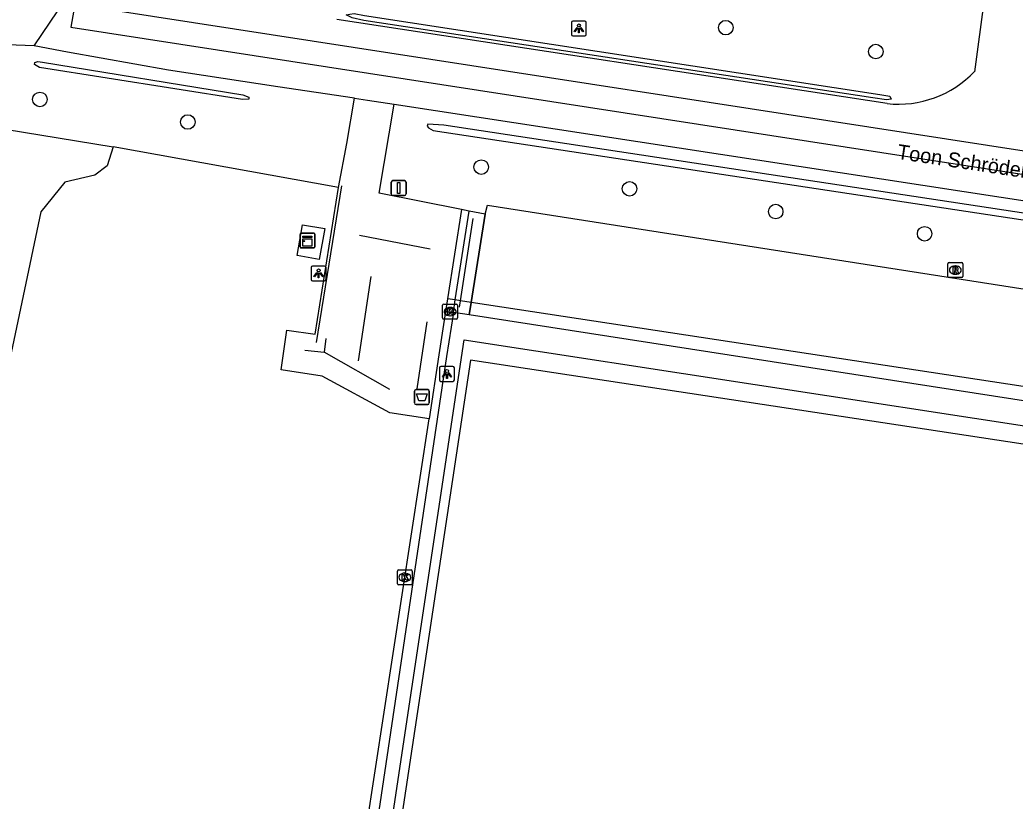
# Model space of a CAD drawing. Extents: x 161094 to 161705, y 379509 to 380907.
# Drawn here: x 161319.9 to 161386.9, y 380124 to 380176.5 of the extents above; entities that cross this region are included whole.
import ezdxf

# ---------------------------------------------------------------- set-up
doc = ezdxf.new("R2010")
doc.units = 0
for name, color, linetype in [('IMGEO_Afvalbak', 7, 'Continuous'), ('IMGEO_Boom', 7, 'Continuous'), ('IMGEO_Grasland_overig', 7, 'Continuous'), ('IMGEO_Greppel_droge_sloot', 7, 'Continuous'), ('IMGEO_Groenvoorziening', 7, 'Continuous'), ('IMGEO_Haag', 7, 'Continuous'), ('IMGEO_Hek', 7, 'Continuous'), ('IMGEO_Kast', 7, 'Continuous'), ('IMGEO_Kolk', 7, 'Continuous'), ('IMGEO_Lichtpunt', 7, 'Continuous'), ('IMGEO_Openbare_ruimte_label', 7, 'Continuous'), ('IMGEO_Rijbaan_lokaal_gesloten', 7, 'Continuous'), ('IMGEO_Rioolput', 7, 'Continuous'), ('IMGEO_Vlaggenmast', 7, 'Continuous'), ('IMGEO_Voetpad_open', 7, 'Continuous')]:
    doc.layers.add(name, color=color, linetype=linetype)

msp = doc.modelspace()

# ---------------------------------------------------------------- linework, layer by layer
at = {"layer": 'IMGEO_Afvalbak'}
for p, q in [((161346.494, 380150.771), (161346.494, 380151.571)), ((161346.494, 380151.571), (161346.494, 380150.771)), ((161346.594, 380151.671), (161347.384, 380151.671)), ((161347.384, 380151.671), (161346.594, 380151.671)), ((161347.484, 380151.571), (161347.484, 380150.771)), ((161347.484, 380150.771), (161347.484, 380151.571)), ((161347.384, 380150.671), (161346.594, 380150.671)), ((161346.594, 380150.671), (161347.384, 380150.671))]:
    msp.add_line(p, q, dxfattribs=at)
msp.add_lwpolyline([(161346.637, 380151.385), (161347.341, 380151.385), (161347.192, 380150.915), (161346.786, 380150.915), (161346.637, 380151.385)], dxfattribs=at)
for centre, start, end in [((161346.594, 380151.571), 90, 180), ((161346.594, 380151.571), 90, 180), ((161347.384, 380151.571), 0, 90), ((161347.384, 380151.571), 360, 90), ((161346.594, 380150.771), 180, 270), ((161346.594, 380150.771), 180, 270), ((161347.384, 380150.771), 270, 0), ((161347.384, 380150.771), 270, 0)]:
    msp.add_arc(centre, 0.1, start, end, dxfattribs=at)
at = {"layer": 'IMGEO_Boom'}
for centre in [(161367.451, 380176.028), (161377.548, 380174.418), (161321.273, 380171.195), (161331.232, 380169.677), (161350.984, 380166.642), (161360.97, 380165.182), (161370.81, 380163.652), (161380.835, 380162.159)]:
    msp.add_circle(centre, 0.489, dxfattribs=at)
at = {"layer": 'IMGEO_Grasland_overig'}
for points in [[(161349.24, 380157.705), (161350.174, 380163.686)], [(161350.174, 380163.686), (161349.657, 380163.789)], [(161349.24, 380157.705), (161348.722, 380157.785)], [(161349.108, 380156.856), (161349.24, 380157.705)], [(161350.313, 380157.541), (161349.581, 380157.653), (161349.24, 380157.705)]]:
    msp.add_lwpolyline(points, dxfattribs=at)
at = {"layer": 'IMGEO_Greppel_droge_sloot'}
for points in [[(161343.135, 380176.847), (161377.814, 380171.54), (161378.489, 380171.421), (161378.582, 380171.222), (161378.264, 380171.169), (161377.338, 380171.315), (161343.079, 380176.509), (161342.296, 380176.684), (161341.888, 380176.892), (161342.13, 380176.942), (161342.43, 380176.975), (161343.135, 380176.847)], [(161334.916, 380171.188), (161321.256, 380173.338), (161320.906, 380173.551), (161320.94, 380173.694), (161321.143, 380173.745), (161321.447, 380173.703), (161334.941, 380171.512), (161335.347, 380171.343), (161335.33, 380171.208), (161334.916, 380171.188)], [(161347.747, 380169.113), (161451.177, 380153.45), (161451.901, 380153.458), (161451.849, 380153.691), (161451.298, 380153.898), (161450.479, 380153.992), (161348.462, 380169.461), (161347.385, 380169.531), (161347.35, 380169.4), (161347.446, 380169.296), (161347.747, 380169.113)]]:
    msp.add_lwpolyline(points, dxfattribs=at)
at = {"layer": 'IMGEO_Groenvoorziening'}
for points in [[(161326.203, 380167.999), (161325.8, 380166.72), (161324.982, 380166.095), (161322.959, 380165.624), (161321.341, 380163.641), (161318.693, 380151.041), (161316.83, 380151.178), (161317.209, 380152.747), (161315.82, 380153.065), (161315.424, 380151.443), (161313.145, 380151.384), (161311.818, 380152.143), (161312.296, 380155.178), (161313.521, 380156.938), (161315.318, 380161.312), (161314.869, 380163.366), (161316.438, 380169.599)], [(161316.438, 380169.599), (161326.203, 380167.999)], [(161341.385, 380165.277), (161326.203, 380167.999)], [(161351.244, 380163.474), (161350.174, 380163.686)], [(161351.244, 380163.474), (161351.407, 380164.082), (161453.112, 380148.201), (161453.472, 380148.145)], [(161350.313, 380157.541), (161351.244, 380163.474)]]:
    msp.add_lwpolyline(points, dxfattribs=at)
at = {"layer": 'IMGEO_Haag'}
for points in [[(161350.18, 380156.696), (161350.313, 380157.541)], [(161411.217, 380148.258), (161350.313, 380157.541)]]:
    msp.add_lwpolyline(points, dxfattribs=at)
at = {"layer": 'IMGEO_Hek'}
for points in [[(161341.587, 380165.383), (161339.884, 380154.846)], [(161349.581, 380157.653), (161350.433, 380163.176)], [(161351.244, 380163.474), (161350.313, 380157.541)], [(161347.539, 380161.125), (161342.795, 380162.031)], [(161342.73, 380153.615), (161343.576, 380159.289)], [(161349.513, 380157.212), (161349.581, 380157.653)], [(161350.313, 380157.541), (161350.18, 380156.696)], [(161349.108, 380156.856), (161348.589, 380156.934)], [(161350.18, 380156.696), (161349.108, 380156.856)], [(161346.676, 380151.73), (161347.35, 380156.236)], [(161335.683, 380060.706), (161349.836, 380155.009), (161408.596, 380146.004), (161401.565, 380099.88), (161400.073, 380089.733)], [(161340.525, 380155.101), (161340.406, 380154.18)], [(161339.1, 380154.32), (161340.406, 380154.18)], [(161344.822, 380151.674), (161340.406, 380154.18)]]:
    msp.add_lwpolyline(points, dxfattribs=at)
at = {"layer": 'IMGEO_Kast'}
for p, q in [((161338.863, 380162.202), (161339.704, 380162.202)), ((161339.704, 380162.202), (161338.863, 380162.202)), ((161338.788, 380161.277), (161338.788, 380162.118)), ((161338.788, 380162.118), (161338.788, 380161.277)), ((161339.788, 380162.127), (161339.788, 380161.286)), ((161339.788, 380161.286), (161339.788, 380162.127)), ((161339.713, 380161.202), (161338.872, 380161.202)), ((161338.872, 380161.202), (161339.713, 380161.202))]:
    msp.add_line(p, q, dxfattribs=at)
for points in [[(161338.983, 380161.992), (161339.583, 380161.992), (161339.583, 380161.907), (161338.983, 380161.907), (161338.983, 380161.992)], [(161338.983, 380161.817), (161339.583, 380161.817), (161339.583, 380161.328), (161338.983, 380161.328), (161338.983, 380161.817)]]:
    msp.add_lwpolyline(points, dxfattribs=at)
msp.add_circle((161339.067, 380161.666), 0.0377, dxfattribs=at)
for centre, start, end in [((161338.866, 380162.124), 92.4484, 184.28452), ((161338.866, 380162.124), 92.4484, 184.28452), ((161339.71, 380162.124), 2.4484, 94.28452), ((161339.71, 380162.124), 2.4484, 94.28452), ((161338.866, 380161.28), 182.4484, 274.28452), ((161338.866, 380161.28), 182.4484, 274.28452), ((161339.71, 380161.28), 272.4484, 4.28452), ((161339.71, 380161.28), 272.4484, 4.28452)]:
    msp.add_arc(centre, 0.0779, start, end, dxfattribs=at)
at = {"layer": 'IMGEO_Kolk'}
for p, q in [((161348.388, 380156.492), (161348.388, 380157.344)), ((161348.463, 380157.418), (161349.315, 380157.418)), ((161348.876, 380157.198), (161348.901, 380157.198)), ((161349.389, 380157.344), (161349.389, 380156.492)), ((161349.315, 380156.418), (161348.463, 380156.418)), ((161348.899, 380156.638), (161348.874, 380156.638)), ((161345.341, 380138.61), (161345.341, 380139.462)), ((161345.416, 380139.536), (161346.268, 380139.536)), ((161346.342, 380139.462), (161346.342, 380138.61)), ((161345.852, 380138.756), (161345.827, 380138.756)), ((161345.829, 380139.316), (161345.854, 380139.316)), ((161346.268, 380138.536), (161345.416, 380138.536))]:
    msp.add_line(p, q, dxfattribs=at)
for points in [[(161348.388, 380156.492), (161348.388, 380157.344)], [(161348.463, 380157.418), (161349.315, 380157.418)], [(161348.709, 380157.118), (161348.832, 380157.118), (161348.832, 380156.967), (161348.962, 380157.118), (161349.126, 380157.118), (161348.98, 380156.967), (161349.133, 380156.718), (161348.981, 380156.718), (161348.896, 380156.882), (161348.832, 380156.815), (161348.832, 380156.718), (161348.709, 380156.718), (161348.709, 380157.118)], [(161349.389, 380157.344), (161349.389, 380156.492)], [(161349.315, 380156.418), (161348.463, 380156.418)], [(161345.341, 380138.61), (161345.341, 380139.462)], [(161345.416, 380139.536), (161346.268, 380139.536)], [(161346.342, 380139.462), (161346.342, 380138.61)], [(161345.662, 380139.236), (161345.785, 380139.236), (161345.785, 380139.085), (161345.915, 380139.236), (161346.079, 380139.236), (161345.933, 380139.085), (161346.086, 380138.836), (161345.934, 380138.836), (161345.849, 380139), (161345.785, 380138.933), (161345.785, 380138.836), (161345.662, 380138.836), (161345.662, 380139.236)], [(161346.268, 380138.536), (161345.416, 380138.536)]]:
    msp.add_lwpolyline(points, dxfattribs=at)
for centre, start, end in [((161348.465, 380157.342), 91.55205, 178.44795), ((161348.465, 380157.342), 91.55205, 178.44795), ((161349.313, 380157.342), 1.55205, 88.44795), ((161349.313, 380157.342), 1.55205, 88.44795), ((161348.465, 380156.494), 181.55205, 268.44795), ((161348.465, 380156.494), 181.55205, 268.44795), ((161349.313, 380156.494), 271.55205, 358.44795), ((161349.313, 380156.494), 271.55205, 358.44795), ((161345.418, 380139.46), 91.55205, 178.44795), ((161345.418, 380139.46), 91.55205, 178.44795), ((161346.266, 380139.46), 1.55205, 88.44795), ((161346.266, 380139.46), 1.55205, 88.44795), ((161345.418, 380138.612), 181.55205, 268.44795), ((161345.418, 380138.612), 181.55205, 268.44795), ((161346.266, 380138.612), 271.55205, 358.44795), ((161346.266, 380138.612), 271.55205, 358.44795)]:
    msp.add_arc(centre, 0.0765, start, end, dxfattribs=at)
for centre, major_axis, ratio, start_param, end_param in [((161348.875, 380156.918), (-0.387, 0.002), 0.722429, 4.712389, 7.853982), ((161348.9, 380156.918), (-0.39, 0.002), 0.717154, 1.570796, 4.712389), ((161345.828, 380139.036), (-0.387, 0.002), 0.722429, 4.712389, 7.853982), ((161345.853, 380139.036), (-0.39, 0.002), 0.717154, 1.570796, 4.712389)]:
    msp.add_ellipse(centre, major_axis=major_axis, ratio=ratio, start_param=start_param, end_param=end_param, dxfattribs=at)
at = {"layer": 'IMGEO_Lichtpunt'}
for p, q in [((161357.063, 380176.377), (161357.063, 380175.57)), ((161357.063, 380176.377), (161357.063, 380175.57)), ((161357.965, 380176.472), (161357.157, 380176.472)), ((161357.965, 380176.472), (161357.157, 380176.472)), ((161358.059, 380175.57), (161358.059, 380176.377)), ((161358.059, 380175.57), (161358.059, 380176.377)), ((161357.157, 380175.476), (161357.965, 380175.476)), ((161357.157, 380175.476), (161357.965, 380175.476)), ((161339.54, 380159.891), (161339.54, 380159.084)), ((161339.54, 380159.891), (161339.54, 380159.084)), ((161340.442, 380159.986), (161339.634, 380159.986)), ((161340.442, 380159.986), (161339.634, 380159.986)), ((161340.536, 380159.084), (161340.536, 380159.891)), ((161340.536, 380159.084), (161340.536, 380159.891)), ((161339.634, 380158.99), (161340.442, 380158.99)), ((161339.634, 380158.99), (161340.442, 380158.99)), ((161348.181, 380153.125), (161348.181, 380152.318)), ((161348.181, 380153.125), (161348.181, 380152.318)), ((161349.083, 380153.22), (161348.275, 380153.22)), ((161349.083, 380153.22), (161348.275, 380153.22)), ((161349.177, 380152.318), (161349.177, 380153.125)), ((161349.177, 380152.318), (161349.177, 380153.125)), ((161348.275, 380152.224), (161349.083, 380152.224)), ((161348.275, 380152.224), (161349.083, 380152.224))]:
    msp.add_line(p, q, dxfattribs=at)
for points in [[(161357.437, 380176.041), (161357.476, 380176.013), (161357.288, 380175.751), (161357.25, 380175.778), (161357.437, 380176.041)], [(161357.539, 380175.993), (161357.586, 380175.993), (161357.586, 380175.671), (161357.539, 380175.671), (161357.539, 380175.993)], [(161357.649, 380176.013), (161357.687, 380176.04), (161357.874, 380175.778), (161357.835, 380175.75), (161357.649, 380176.013)], [(161339.914, 380159.555), (161339.953, 380159.527), (161339.765, 380159.265), (161339.727, 380159.292), (161339.914, 380159.555)], [(161340.016, 380159.507), (161340.063, 380159.507), (161340.063, 380159.185), (161340.016, 380159.185), (161340.016, 380159.507)], [(161340.126, 380159.527), (161340.164, 380159.554), (161340.351, 380159.292), (161340.312, 380159.264), (161340.126, 380159.527)], [(161348.555, 380152.789), (161348.594, 380152.761), (161348.406, 380152.499), (161348.368, 380152.526), (161348.555, 380152.789)], [(161348.657, 380152.741), (161348.704, 380152.741), (161348.704, 380152.419), (161348.657, 380152.419), (161348.657, 380152.741)], [(161348.767, 380152.761), (161348.805, 380152.788), (161348.992, 380152.526), (161348.953, 380152.498), (161348.767, 380152.761)]]:
    msp.add_lwpolyline(points, dxfattribs=at)
for centre in [(161357.562, 380176.175), (161340.039, 380159.689), (161348.68, 380152.923)]:
    msp.add_circle(centre, 0.0994, dxfattribs=at)
for centre, start, end in [((161357.157, 380176.377), 90, 180), ((161357.157, 380176.377), 90, 180), ((161357.965, 380176.377), 0, 90), ((161357.965, 380176.377), 0, 90), ((161357.157, 380175.57), 180, 270), ((161357.157, 380175.57), 180, 270), ((161357.965, 380175.57), 270, 0), ((161357.965, 380175.57), 270, 360), ((161339.634, 380159.891), 90, 180), ((161339.634, 380159.891), 90, 180), ((161340.442, 380159.891), 0, 90), ((161340.442, 380159.891), 0, 90), ((161339.634, 380159.084), 180, 270), ((161339.634, 380159.084), 180, 270), ((161340.442, 380159.084), 270, 0), ((161340.442, 380159.084), 270, 360), ((161348.275, 380153.125), 90, 180), ((161348.275, 380153.125), 90, 180), ((161349.083, 380153.125), 0, 90), ((161349.083, 380153.125), 0, 90), ((161348.275, 380152.318), 180, 270), ((161348.275, 380152.318), 180, 270), ((161349.083, 380152.318), 270, 0), ((161349.083, 380152.318), 270, 360)]:
    msp.add_arc(centre, 0.0946, start, end, dxfattribs=at)
at = {"layer": 'IMGEO_Rijbaan_lokaal_gesloten'}
for points in [[(161320.891, 380174.795), (161324.072, 380179.541)], [(161384.853, 380177.941), (161384.188, 380173.066)], [(161323.619, 380177.579), (161323.363, 380176.065), (161397.984, 380164.531), (161445.878, 380157.188), (161446.09, 380158.691), (161398.278, 380166.048), (161323.619, 380177.579)], [(161378.314, 380170.916), (161341.266, 380176.581)], [(161320.891, 380174.795), (161319.074, 380174.881)], [(161342.454, 380171.274), (161337.287, 380172.056), (161329.938, 380173.17), (161323.138, 380174.385), (161320.891, 380174.795)], [(161342.454, 380171.274), (161343.323, 380171.142), (161345.123, 380170.869)], [(161345.123, 380170.869), (161454.384, 380154.139)]]:
    msp.add_lwpolyline(points, dxfattribs=at)
msp.add_arc((161379.05, 380178.004), 7.126, 264.06907, 316.13818, dxfattribs=at)
at = {"layer": 'IMGEO_Rioolput'}
for p, q in [((161382.476, 380160.214), (161383.328, 380160.214)), ((161382.401, 380159.288), (161382.401, 380160.14)), ((161382.889, 380159.994), (161382.914, 380159.994)), ((161383.402, 380160.14), (161383.402, 380159.288)), ((161383.328, 380159.214), (161382.476, 380159.214)), ((161382.912, 380159.434), (161382.887, 380159.434))]:
    msp.add_line(p, q, dxfattribs=at)
for points in [[(161382.476, 380160.214), (161383.328, 380160.214)], [(161382.401, 380159.288), (161382.401, 380160.14)], [(161382.99, 380159.912), (161382.738, 380159.914), (161382.738, 380159.514)], [(161382.738, 380159.514), (161382.862, 380159.514), (161382.862, 380159.676), (161382.873, 380159.676)], [(161382.916, 380159.833), (161382.862, 380159.833), (161382.862, 380159.752)], [(161382.862, 380159.752), (161382.914, 380159.752)], [(161382.92, 380159.647), (161382.991, 380159.514), (161383.131, 380159.514), (161383.066, 380159.64)], [(161383.402, 380160.14), (161383.402, 380159.288)], [(161383.328, 380159.214), (161382.476, 380159.214)]]:
    msp.add_lwpolyline(points, dxfattribs=at)
for centre, radius, start, end in [((161382.478, 380160.138), 0.0765, 91.55205, 178.44795), ((161382.478, 380160.138), 0.0765, 91.55205, 178.44795), ((161383.326, 380160.138), 0.0765, 1.55205, 88.44795), ((161383.326, 380160.138), 0.0765, 1.55205, 88.44795), ((161382.872, 380159.623), 0.0533, 26.02933, 88.69889), ((161382.898, 380159.941), 0.19, 274.7715, 282.96867), ((161382.922, 380159.737), 0.0964, 77.00612, 93.18647), ((161382.936, 380159.794), 0.0378, 276.66336, 79.67722), ((161382.989, 380159.802), 0.109, 350.36119, 89.41601), ((161382.987, 380159.802), 0.112, 277.58423, 350.98172), ((161382.971, 380159.587), 0.108, 29.51342, 73.79051), ((161382.478, 380159.29), 0.0765, 181.55205, 268.44795), ((161382.478, 380159.29), 0.0765, 181.55205, 268.44795), ((161383.326, 380159.29), 0.0765, 271.55205, 358.44795), ((161383.326, 380159.29), 0.0765, 271.55205, 358.44795)]:
    msp.add_arc(centre, radius, start, end, dxfattribs=at)
for centre, major_axis, ratio, start_param, end_param in [((161382.888, 380159.714), (-0.387, 0.002), 0.722429, 4.712389, 7.853982), ((161382.913, 380159.714), (-0.39, 0.002), 0.717154, 1.570796, 4.712389)]:
    msp.add_ellipse(centre, major_axis=major_axis, ratio=ratio, start_param=start_param, end_param=end_param, dxfattribs=at)
at = {"layer": 'IMGEO_Vlaggenmast'}
for p, q in [((161344.933, 380164.836), (161344.933, 380165.636)), ((161344.933, 380165.636), (161344.933, 380164.836)), ((161345.033, 380165.736), (161345.823, 380165.736)), ((161345.823, 380165.736), (161345.033, 380165.736)), ((161345.923, 380165.636), (161345.923, 380164.836)), ((161345.923, 380164.836), (161345.923, 380165.636)), ((161345.823, 380164.736), (161345.033, 380164.736)), ((161345.033, 380164.736), (161345.823, 380164.736))]:
    msp.add_line(p, q, dxfattribs=at)
msp.add_lwpolyline([(161345.353, 380165.611), (161345.503, 380165.611), (161345.503, 380164.861), (161345.353, 380164.861), (161345.353, 380165.611)], dxfattribs=at)
for centre, start, end in [((161345.033, 380165.636), 90, 180), ((161345.033, 380165.636), 90, 180), ((161345.823, 380165.636), 0, 90), ((161345.823, 380165.636), 360, 90), ((161345.033, 380164.836), 180, 270), ((161345.033, 380164.836), 180, 270), ((161345.823, 380164.836), 270, 0), ((161345.823, 380164.836), 270, 0)]:
    msp.add_arc(centre, 0.1, start, end, dxfattribs=at)
at = {"layer": 'IMGEO_Voetpad_open'}
for points in [[(161341.385, 380165.277), (161341.942, 380168.24), (161342.454, 380171.274)], [(161349.657, 380163.789), (161344.11, 380164.89), (161345.123, 380170.869)], [(161347.475, 380149.706), (161344.834, 380150.112), (161340.287, 380152.57), (161337.51, 380152.994), (161337.906, 380155.667), (161339.811, 380155.395), (161341.385, 380165.277)], [(161349.657, 380163.789), (161348.722, 380157.785)], [(161338.583, 380160.705), (161338.955, 380162.758), (161340.452, 380162.501), (161340.074, 380160.436), (161338.583, 380160.705)], [(161348.722, 380157.785), (161348.589, 380156.934)], [(161349.108, 380156.856), (161348.646, 380153.898), (161340.642, 380100.124), (161338.363, 380084.836)], [(161348.589, 380156.934), (161348.133, 380154.002), (161347.475, 380149.706)], [(161348.589, 380156.934), (161349.108, 380156.856)], [(161350.18, 380156.696), (161349.108, 380156.856)], [(161411.067, 380147.269), (161408.469, 380147.669), (161350.18, 380156.696)], [(161399.724, 380087.358), (161393.849, 380047.412), (161370.361, 380050.99), (161335.04, 380056.371), (161335.683, 380060.706), (161349.836, 380155.009), (161408.596, 380146.004), (161401.565, 380099.88), (161400.073, 380089.733)], [(161407.836, 380144.894), (161350.254, 380153.646), (161342.156, 380099.977), (161335.817, 380057.581), (161393.41, 380048.84), (161400.945, 380100.026), (161407.836, 380144.894)], [(161338.363, 380084.836), (161338.156, 380084.87), (161338.298, 380088.072), (161338.299, 380088.093), (161343.241, 380122.073), (161347.475, 380149.706)]]:
    msp.add_lwpolyline(points, dxfattribs=at)

# ---------------------------------------------------------------- texts
at = {"layer": 'IMGEO_Openbare_ruimte_label'}
msp.add_text('Toon Schröderlaan', height=1, rotation=351.43241, dxfattribs=at).set_placement((161378.935, 380167.207))

doc.saveas('drawing.dxf')
